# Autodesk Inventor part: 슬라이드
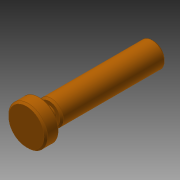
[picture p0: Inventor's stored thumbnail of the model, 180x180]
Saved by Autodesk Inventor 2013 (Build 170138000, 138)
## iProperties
Created: 2015-09
Part Number: 슬라이드
Material: 강철, 연강
Document SubType Name: Modeling
Designer: mduedu
Density: 1 g/cm^3
Author: mduedu
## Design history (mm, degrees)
sketch "스케치1"
  geometry: C1 r 11 at (0, 0); 1 further point
  constraints: 1 centre point, 1 coincident
  dimensions: "d0" = 22 diameter of C1
extrude "돌출1" new body sketch "스케치1" distance "d1" = 8; taper "d2" = 0 deg
sketch "스케치2"
  geometry: C1 r 4 at (0, 0); 1 further point
  constraints: 1 centre point, 1 coincident
  dimensions: "d3" = 8 diameter of C1
extrude "돌출2" join sketch "스케치2" distance "d4" = 5; taper "d5" = 0 deg
sketch "스케치3"
  geometry: C1 r 7 at (0, 0); 1 further point
  constraints: 1 centre point, 1 coincident
  dimensions: "d6" = 14 diameter of C1
extrude "돌출3" join sketch "스케치3" distance "d7" = 59; taper "d8" = 0 deg
hole "구멍1" diameter "d11" = 4.134; stored, may be unused: countersink angle "d15" = 90 deg, drill point angle "d17" = 118 deg; dims "d9" = 10, "d10" = 10, "d12" = 9, "d13" = 4, "d14" = 2, "d16" = 12
chamfer "모따기1" distance "d18" = 1; stored, may be unused: second distance "d19" = 2, angle "d20" = 45 deg
node "솔리드1"
